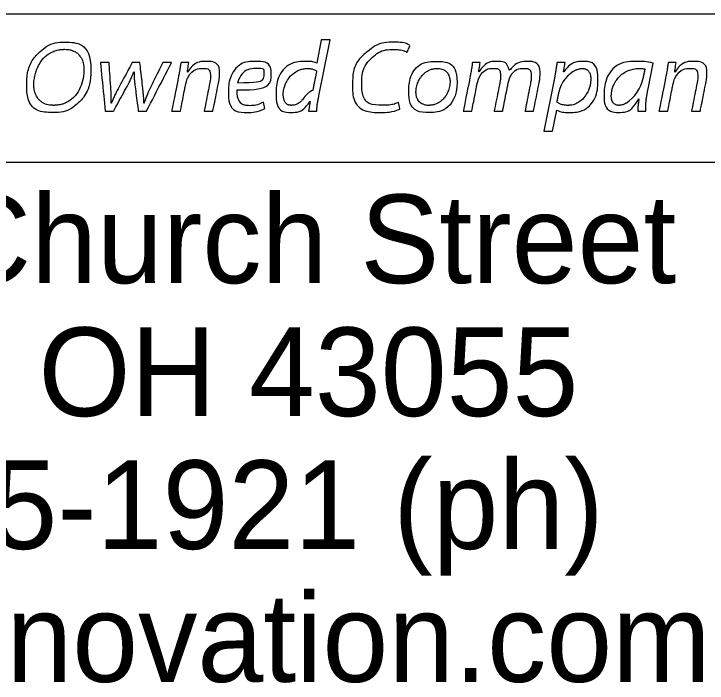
# Model space of a CAD drawing. Extents: x 0 to 34, y 0 to 22.
# Drawn here: x 32.7 to 33.336, y 2.727 to 3.341 of the extents above; entities that cross this region are included whole.
import ezdxf

# ---------------------------------------------------------------- set-up
doc = ezdxf.new("R2010")
doc.units = 0
doc.layers.add('SH_Data', color=7, linetype='Continuous')

msp = doc.modelspace()

# ---------------------------------------------------------------- linework, layer by layer
at = {"layer": 'SH_Data'}
for p, q in [((32.05557, 3.3407), (33.44039, 3.3407)), ((32.72917, 3.30154), (32.72917, 3.30154)), ((33.28217, 3.27206), (33.28692, 3.29536)), ((32.97559, 3.28963), (32.97816, 3.28846)), ((33.27357, 3.2629), (33.27376, 3.2629)), ((32.93057, 3.25393), (32.92941, 3.25966)), ((33.27269, 3.25134), (33.28014, 3.25134)), ((32.04831, 3.20477), (33.43313, 3.20477))]:
    msp.add_line(p, q, dxfattribs=at)
for points in [[(32.98022, 3.26549), (32.99048, 3.317), (32.98244, 3.317), (32.97828, 3.29555)], [(33.20485, 3.28768), (33.20466, 3.28768), (33.20601, 3.29619), (33.19865, 3.29619)], [(33.19604, 3.28019), (33.18665, 3.23303), (33.19459, 3.23303), (33.19837, 3.25236), (33.19856, 3.25236)], [(32.97189, 3.26022), (32.97208, 3.26022), (32.97083, 3.25134), (32.97818, 3.25134)], [(33.2017, 3.25804), (33.1986, 3.25976), (33.1986, 3.25976)], [(33.1986, 3.25976), (33.1986, 3.25976)]]:
    msp.add_lwpolyline(points, dxfattribs=at)
for centre, radius, start, end in [((33.22864, 3.26327), 0.02878, 114.69426, 168.74282), ((33.2423, 3.28901), 0.03596, 303.10986, 348.48361), ((32.9819, 3.25354), 0.01853, 113.18842, 146.28187), ((33.2423, 3.28901), 0.03596, 300.9319793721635, 300.93198431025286)]:
    msp.add_arc(centre, radius, start, end, dxfattribs=at)
for points, degree in [([(32.77117, 3.28917), (32.77117, 3.30248), (32.7641, 3.31469), (32.74659, 3.31469), (32.73836, 3.31469), (32.73023, 3.31145), (32.72472, 3.30627), (32.71678, 3.29878), (32.71223, 3.28667), (32.71223, 3.27566), (32.71223, 3.26244), (32.72017, 3.25032), (32.73701, 3.25032), (32.74601, 3.25032), (32.75356, 3.25356), (32.75936, 3.25902), (32.7671, 3.26641), (32.77117, 3.27834), (32.77117, 3.28917)], 3), ([(33.05444, 3.25337), (33.05077, 3.2518), (33.04486, 3.25032), (33.03751, 3.25032), (33.02106, 3.25032), (33.01109, 3.26031), (33.01109, 3.27622), (33.01109, 3.28796), (33.01602, 3.29915), (33.02502, 3.30627), (33.0317, 3.31173), (33.04003, 3.31469), (33.04961, 3.31469), (33.05686, 3.31469), (33.06199, 3.31293), (33.06374, 3.31164), (33.06374, 3.31164), (33.06112, 3.30544), (33.06112, 3.30544), (33.0587, 3.30683), (33.05406, 3.30803), (33.04825, 3.30803), (33.04148, 3.30803), (33.0346, 3.30554), (33.02957, 3.301), (33.02347, 3.29555), (33.01961, 3.28676), (33.01961, 3.27733), (33.01961, 3.26614), (33.02493, 3.25698), (33.03944, 3.25698), (33.04438, 3.25698), (33.0498, 3.25791), (33.05338, 3.25966), (33.05338, 3.25966), (33.05444, 3.25337), (33.05444, 3.25337)], 3), ([(32.72917, 3.30154), (32.73125, 3.3035), (32.73397, 3.30519), (32.7385, 3.30695), (32.74008, 3.30741), (32.74251, 3.30788), (32.74332, 3.30799), (32.74455, 3.30811), (32.74516, 3.30816), (32.74587, 3.30818), (32.74623, 3.30819), (32.74641, 3.30819), (32.7465, 3.30819), (32.74654, 3.30819), (32.74656, 3.30819), (32.74656, 3.30819), (32.75021, 3.30819), (32.75302, 3.30757), (32.75745, 3.30565), (32.75911, 3.30436), (32.76182, 3.30113), (32.76287, 3.29915), (32.7643, 3.29454), (32.76467, 3.29192), (32.76467, 3.28917)], 3), ([(32.75489, 3.26373), (32.75313, 3.26208), (32.75121, 3.26071), (32.74701, 3.25855), (32.74474, 3.25776), (32.74102, 3.25706), (32.73972, 3.25691), (32.73803, 3.25684), (32.7376, 3.25682), (32.73714, 3.25682), (32.73704, 3.25682), (32.73699, 3.25682), (32.73694, 3.25682), (32.73682, 3.25682), (32.73642, 3.25682), (32.73603, 3.25684), (32.7345, 3.25691), (32.73338, 3.25705), (32.73025, 3.25766), (32.72851, 3.25833), (32.72552, 3.26004), (32.72427, 3.26109), (32.72212, 3.26354), (32.72123, 3.26496), (32.71983, 3.26815), (32.71932, 3.26991), (32.71888, 3.27272), (32.71879, 3.27369), (32.71874, 3.27492), (32.71873, 3.27517), (32.71873, 3.27554), (32.71873, 3.27566), (32.71873, 3.27588), (32.71873, 3.27642), (32.71875, 3.27697), (32.71886, 3.27917), (32.71909, 3.28097), (32.72015, 3.28638), (32.72139, 3.28998), (32.72471, 3.29644), (32.72681, 3.29931), (32.72917, 3.30154)], 3), ([(32.78782, 3.2961), (32.78782, 3.2961), (32.78946, 3.27095), (32.78946, 3.27095), (32.78985, 3.2654), (32.78975, 3.26253), (32.78965, 3.25892), (32.78965, 3.25892), (32.78995, 3.25892), (32.78995, 3.25892), (32.79101, 3.26179), (32.79275, 3.26567), (32.79508, 3.27011), (32.79508, 3.27011), (32.80901, 3.2961), (32.80901, 3.2961), (32.80901, 3.2961), (32.81598, 3.2961), (32.81598, 3.2961), (32.81598, 3.2961), (32.81889, 3.27058), (32.81889, 3.27058), (32.81936, 3.26567), (32.81975, 3.26188), (32.81966, 3.25892), (32.81966, 3.25892), (32.81985, 3.25892), (32.81985, 3.25892), (32.82111, 3.26253), (32.82246, 3.26595), (32.8243, 3.27021), (32.8243, 3.27021), (32.83698, 3.2961), (32.83698, 3.2961), (32.83698, 3.2961), (32.84511, 3.2961), (32.84511, 3.2961), (32.84511, 3.2961), (32.82198, 3.25134), (32.82198, 3.25134), (32.82198, 3.25134), (32.81453, 3.25134), (32.81453, 3.25134), (32.81453, 3.25134), (32.81143, 3.27566), (32.81143, 3.27566), (32.81095, 3.27983), (32.81075, 3.28362), (32.81075, 3.2875), (32.81075, 3.2875), (32.81056, 3.2875), (32.81056, 3.2875), (32.80862, 3.28325), (32.80727, 3.27983), (32.80514, 3.27585), (32.80514, 3.27585), (32.79169, 3.25134), (32.79169, 3.25134), (32.79169, 3.25134), (32.78423, 3.25134), (32.78423, 3.25134), (32.78423, 3.25134), (32.77988, 3.2961), (32.77988, 3.2961), (32.77988, 3.2961), (32.78782, 3.2961), (32.78782, 3.2961)], 3), ([(32.84511, 3.25134), (32.84511, 3.25134), (32.8514, 3.28306), (32.8514, 3.28306), (32.85247, 3.28806), (32.85304, 3.2924), (32.85362, 3.2961), (32.85362, 3.2961), (32.86079, 3.2961), (32.86079, 3.2961), (32.86079, 3.2961), (32.85963, 3.28731), (32.85963, 3.28731), (32.85963, 3.28731), (32.85982, 3.28731), (32.85982, 3.28731), (32.86398, 3.29361), (32.87027, 3.29712), (32.87714, 3.29712), (32.88276, 3.29712), (32.88905, 3.29407), (32.88905, 3.28463), (32.88905, 3.28269), (32.88866, 3.27983), (32.88818, 3.27742), (32.88818, 3.27742), (32.88295, 3.25134), (32.88295, 3.25134), (32.88295, 3.25134), (32.87492, 3.25134), (32.87492, 3.25134), (32.87492, 3.25134), (32.88005, 3.27714), (32.88005, 3.27714), (32.88043, 3.2789), (32.88073, 3.28103), (32.88073, 3.28288), (32.88073, 3.28741), (32.87889, 3.29074), (32.87337, 3.29074), (32.86766, 3.29074), (32.85953, 3.28417), (32.8574, 3.27307), (32.8574, 3.27307), (32.85314, 3.25134), (32.85314, 3.25134), (32.85314, 3.25134), (32.84511, 3.25134), (32.84511, 3.25134)], 3), ([(32.9054, 3.27104), (32.92273, 3.27076), (32.93657, 3.2739), (32.93657, 3.28565), (32.93657, 3.29203), (32.93173, 3.29712), (32.92282, 3.29712), (32.90773, 3.29712), (32.89728, 3.28186), (32.89728, 3.26836), (32.89728, 3.25846), (32.90269, 3.25032), (32.91508, 3.25032), (32.92137, 3.25032), (32.92708, 3.25199), (32.93057, 3.25393)], 3), ([(32.97828, 3.29555), (32.97625, 3.29647), (32.97296, 3.29712), (32.96996, 3.29712), (32.95341, 3.29712), (32.94102, 3.28251), (32.94102, 3.2666), (32.94102, 3.25744), (32.94596, 3.25032), (32.95505, 3.25032), (32.96173, 3.25032), (32.96763, 3.25384), (32.97189, 3.26022)], 3), ([(33.107, 3.27844), (33.107, 3.28796), (33.10139, 3.29712), (33.08871, 3.29712), (33.07351, 3.29712), (33.06277, 3.28343), (33.06277, 3.26873), (33.06277, 3.25865), (33.06935, 3.25032), (33.08106, 3.25032), (33.09674, 3.25032), (33.107, 3.26466), (33.107, 3.27844)], 3), ([(33.11261, 3.25134), (33.11261, 3.25134), (33.1189, 3.28306), (33.1189, 3.28306), (33.11987, 3.28806), (33.12055, 3.2924), (33.12103, 3.2961), (33.12103, 3.2961), (33.1281, 3.2961), (33.1281, 3.2961), (33.1281, 3.2961), (33.12684, 3.28768), (33.12684, 3.28768), (33.12684, 3.28768), (33.12713, 3.28768), (33.12713, 3.28768), (33.13149, 3.29388), (33.13739, 3.29712), (33.14359, 3.29712), (33.15074, 3.29712), (33.15413, 3.29277), (33.15452, 3.28713), (33.15868, 3.29361), (33.16468, 3.29703), (33.17174, 3.29712), (33.17717, 3.29712), (33.18307, 3.29379), (33.18307, 3.28537), (33.18307, 3.28325), (33.18278, 3.28029), (33.1823, 3.27779), (33.1823, 3.27779), (33.17707, 3.25134), (33.17707, 3.25134), (33.17707, 3.25134), (33.16923, 3.25134), (33.16923, 3.25134), (33.16923, 3.25134), (33.17426, 3.27714), (33.17426, 3.27714), (33.17465, 3.27881), (33.17494, 3.28112), (33.17494, 3.28297), (33.17494, 3.28768), (33.1731, 3.29074), (33.16787, 3.29074), (33.16207, 3.29074), (33.1552, 3.28426), (33.15326, 3.27428), (33.15326, 3.27428), (33.14871, 3.25134), (33.14871, 3.25134), (33.14871, 3.25134), (33.14097, 3.25134), (33.14097, 3.25134), (33.14097, 3.25134), (33.1462, 3.27761), (33.1462, 3.27761), (33.14658, 3.27955), (33.14678, 3.2813), (33.14678, 3.28306), (33.14678, 3.28685), (33.14571, 3.29074), (33.13981, 3.29074), (33.1339, 3.29074), (33.12665, 3.28334), (33.12481, 3.27381), (33.12481, 3.27381), (33.12045, 3.25134), (33.12045, 3.25134), (33.12045, 3.25134), (33.11261, 3.25134), (33.11261, 3.25134)], 3), ([(33.19865, 3.29619), (33.19798, 3.29166), (33.19701, 3.28556), (33.19604, 3.28019)], 2), ([(33.19856, 3.25236), (33.2004, 3.25134), (33.20369, 3.25032), (33.20872, 3.25032), (33.2243, 3.25032), (33.23611, 3.26521), (33.23611, 3.28093), (33.23611, 3.28916), (33.23185, 3.29712), (33.22169, 3.29712), (33.2153, 3.29712), (33.20911, 3.29351), (33.20485, 3.28768)], 3), ([(33.28692, 3.29536), (33.28373, 3.29638), (33.27879, 3.29712), (33.27434, 3.29712), (33.25392, 3.29712), (33.24192, 3.28066), (33.24192, 3.26512), (33.24192, 3.25661), (33.24714, 3.25032), (33.25537, 3.25032), (33.26204, 3.25032), (33.26843, 3.25365), (33.27357, 3.2629)], 3), ([(33.29215, 3.25134), (33.29215, 3.25134), (33.29844, 3.28306), (33.29844, 3.28306), (33.2995, 3.28806), (33.30008, 3.2924), (33.30066, 3.2961), (33.30066, 3.2961), (33.30782, 3.2961), (33.30782, 3.2961), (33.30782, 3.2961), (33.30666, 3.28731), (33.30666, 3.28731), (33.30666, 3.28731), (33.30686, 3.28731), (33.30686, 3.28731), (33.31102, 3.29361), (33.31731, 3.29712), (33.32418, 3.29712), (33.32979, 3.29712), (33.33608, 3.29407), (33.33608, 3.28463), (33.33608, 3.28269), (33.3357, 3.27983), (33.33521, 3.27742), (33.33521, 3.27742), (33.32999, 3.25134), (33.32999, 3.25134), (33.32999, 3.25134), (33.32196, 3.25134), (33.32196, 3.25134), (33.32196, 3.25134), (33.32708, 3.27714), (33.32708, 3.27714), (33.32747, 3.2789), (33.32776, 3.28103), (33.32776, 3.28288), (33.32776, 3.28741), (33.32592, 3.29074), (33.32041, 3.29074), (33.3147, 3.29074), (33.30656, 3.28417), (33.30444, 3.27307), (33.30444, 3.27307), (33.30018, 3.25134), (33.30018, 3.25134), (33.30018, 3.25134), (33.29215, 3.25134), (33.29215, 3.25134)], 3), ([(32.76467, 3.28917), (32.76467, 3.28457), (32.76379, 3.27961), (32.7604, 3.27062), (32.7579, 3.26662), (32.75489, 3.26373)], 3), ([(32.90543, 3.27758), (32.90822, 3.28502), (32.91441, 3.29062), (32.92282, 3.29062), (32.92894, 3.29062), (32.93007, 3.28943), (32.93007, 3.28565), (32.93007, 3.27966), (32.92337, 3.27762), (32.90543, 3.27758)], 3), ([(32.96648, 3.26383), (32.96542, 3.26223), (32.96428, 3.26094), (32.96193, 3.25893), (32.96073, 3.25819), (32.95826, 3.25718), (32.95698, 3.2569), (32.95527, 3.25682), (32.9549, 3.25682), (32.95423, 3.25685), (32.95392, 3.25688), (32.95304, 3.25701), (32.95254, 3.25715), (32.95121, 3.25768), (32.95053, 3.25816), (32.94927, 3.25955), (32.94871, 3.26048), (32.94786, 3.26289), (32.94758, 3.26437), (32.94748, 3.26772), (32.94762, 3.26934), (32.94849, 3.27415), (32.9497, 3.27723), (32.95312, 3.28265), (32.95533, 3.285), (32.96042, 3.28856), (32.96328, 3.28978), (32.96719, 3.29045), (32.96799, 3.29054), (32.96962, 3.29063), (32.97045, 3.29063), (32.97222, 3.29048), (32.97314, 3.29034), (32.97468, 3.28998), (32.97532, 3.28975), (32.97559, 3.28963)], 3), ([(32.97816, 3.28846), (32.97674, 3.28131), (32.9754, 3.27459), (32.9746, 3.27057)], 2), ([(33.06927, 3.26873), (33.06927, 3.27161), (33.0698, 3.27447), (33.07176, 3.27974), (33.07319, 3.28215), (33.0767, 3.28618), (33.07877, 3.28779), (33.08221, 3.28945), (33.08342, 3.28987), (33.08533, 3.29031), (33.08598, 3.29043), (33.08698, 3.29054), (33.08749, 3.29058), (33.08809, 3.29061), (33.08836, 3.29062), (33.08853, 3.29062), (33.08863, 3.29062), (33.0911, 3.29062), (33.0929, 3.2902), (33.09573, 3.28896), (33.09679, 3.28815), (33.09856, 3.28608), (33.09926, 3.28482), (33.10024, 3.28186), (33.1005, 3.28018), (33.1005, 3.27844)], 3), ([(33.21662, 3.28942), (33.21694, 3.28957), (33.21725, 3.2897), (33.21889, 3.29033), (33.22021, 3.29059), (33.22159, 3.29062), (33.22166, 3.29062), (33.22187, 3.29062), (33.22218, 3.29061), (33.22247, 3.29059), (33.22302, 3.29055), (33.22336, 3.2905), (33.22431, 3.29032), (33.22483, 3.29015), (33.22619, 3.28954), (33.22686, 3.28901), (33.22807, 3.28752), (33.2286, 3.28654), (33.22936, 3.28413), (33.22958, 3.28272), (33.22961, 3.28105), (33.22961, 3.28086), (33.22961, 3.28044), (33.22959, 3.2798), (33.2295, 3.27833), (33.22933, 3.27707), (33.22855, 3.27292), (33.22729, 3.26972), (33.22377, 3.26416), (33.22153, 3.26181), (33.21651, 3.25837), (33.21375, 3.25729), (33.21039, 3.25689), (33.20983, 3.25685), (33.20916, 3.25682), (33.20887, 3.25682), (33.20874, 3.25682), (33.20872, 3.25682), (33.20864, 3.25682), (33.20851, 3.25682), (33.20708, 3.25683), (33.20591, 3.25694), (33.20317, 3.25737), (33.20208, 3.25784), (33.2017, 3.25804)], 3), ([(33.26078, 3.25816), (33.26075, 3.25815), (33.26073, 3.25813), (33.25958, 3.25752), (33.25848, 3.25716), (33.25671, 3.25687), (33.25609, 3.25683), (33.25514, 3.25682), (33.25479, 3.25683), (33.25418, 3.25689), (33.2539, 3.25694), (33.25256, 3.25723), (33.25175, 3.25764), (33.25036, 3.25881), (33.24976, 3.25958), (33.24881, 3.26168), (33.24849, 3.26301), (33.24842, 3.26478), (33.24842, 3.26499), (33.24842, 3.26537), (33.24842, 3.26593), (33.24849, 3.26726), (33.24863, 3.2684), (33.24926, 3.27222), (33.25034, 3.27526), (33.25354, 3.28079), (33.25565, 3.28328), (33.26078, 3.28731), (33.26378, 3.28885), (33.26904, 3.29021), (33.27092, 3.2905), (33.27395, 3.29063), (33.27499, 3.29063), (33.27711, 3.29053), (33.2782, 3.29044), (33.27926, 3.29031)], 3), ([(33.27926, 3.29031), (33.27873, 3.28769), (33.2781, 3.28463), (33.27753, 3.28183)], 2), ([(33.1005, 3.27844), (33.1005, 3.2758), (33.1, 3.27306), (33.0981, 3.26789), (33.0967, 3.26546), (33.09323, 3.26139), (33.09117, 3.25974), (33.0877, 3.25804), (33.08649, 3.2576), (33.08454, 3.25714), (33.08388, 3.25702), (33.08285, 3.2569), (33.08232, 3.25686), (33.0817, 3.25683), (33.08138, 3.25682), (33.08125, 3.25682), (33.08115, 3.25682), (33.0811, 3.25682), (33.07891, 3.25682), (33.07717, 3.2572), (33.07433, 3.25837), (33.07321, 3.25917), (33.07135, 3.26117), (33.07061, 3.26238), (33.06957, 3.26526), (33.06927, 3.26691), (33.06927, 3.26873)], 3), ([(32.92941, 3.25966), (32.9265, 3.25818), (32.92234, 3.25652), (32.91682, 3.25652), (32.91198, 3.25652), (32.90821, 3.25855), (32.90637, 3.26253), (32.90531, 3.26493), (32.90502, 3.2691), (32.9054, 3.27104)], 3), ([(33.1986, 3.25976), (33.19925, 3.26301), (33.19987, 3.26614), (33.20042, 3.26889)], 2), ([(33.28014, 3.25134), (33.27995, 3.25633), (33.28063, 3.26429), (33.28217, 3.27206)], 2), ([(32.97818, 3.25134), (32.97847, 3.25569), (32.97925, 3.26087), (32.98022, 3.26549)], 2), ([(33.27376, 3.2629), (33.27318, 3.25828), (33.27269, 3.25402), (33.27269, 3.25134)], 2), ([(33.26194, 3.25889), (33.26155, 3.25861), (33.26116, 3.25837), (33.26078, 3.25816)], 2)]:
    msp.add_open_spline(points, degree=degree, dxfattribs=at)

# ---------------------------------------------------------------- texts
for s, p in [('88 West Church Street', (32.20907, 3.09376)), ('Newark, OH 43055', (32.29431, 2.97189)), ('(740) 345-1921 (ph)', (32.27515, 2.85001)), ('www.adrinnovation.com', (32.18636, 2.72814))]:
    msp.add_text(s, height=0.0812498, dxfattribs=at).set_placement(p)

doc.saveas('drawing.dxf')
